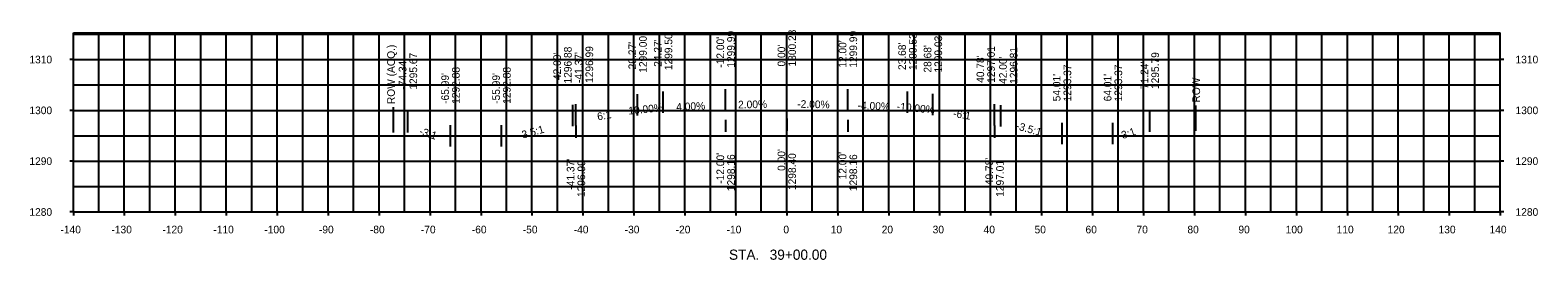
# Model space of a CAD drawing. Extents: x -148 to 147, y 1271 to 1316.
import ezdxf

# ---------------------------------------------------------------- set-up
doc = ezdxf.new("R2010")
doc.units = 0
for name, color, linetype in [('brgPreNewPavement', 7, 'Continuous'), ('BridgeSubstructure', 7, 'Continuous'), ('BridgeSuperStructure', 7, 'Continuous'), ('Default', 7, 'Continuous'), ('OBD_Bridge_Piling', 7, 'Continuous'), ('OBD_D_Super', 7, 'Continuous')]:
    doc.layers.add(name, color=color, linetype=linetype)

msp = doc.modelspace()

# ---------------------------------------------------------------- linework, layer by layer
at = {"layer": 'brgPreNewPavement'}
for p, q in [((-77.18, 1295.64), (-77.18, 1300.64)), ((80.26, 1295.96), (80.26, 1300.96))]:
    msp.add_line(p, q, dxfattribs=at)
at = {"layer": 'BridgeSubstructure'}
for p, q in [((-130, 1280), (-130, 1315.23)), ((-120, 1280), (-120, 1315.23)), ((-110, 1280), (-110, 1315.23)), ((-100, 1280), (-100, 1315.23)), ((-90, 1280), (-90, 1315.23)), ((-80, 1280), (-80, 1315.23)), ((-70, 1280), (-70, 1315.23)), ((-60, 1280), (-60, 1315.23)), ((-50, 1280), (-50, 1315.23)), ((-40, 1280), (-40, 1315.23)), ((-30, 1280), (-30, 1315.23)), ((-20, 1280), (-20, 1315.23)), ((-10, 1280), (-10, 1315.23)), ((0, 1280), (0, 1315.23)), ((10, 1280), (10, 1315.23)), ((20, 1280), (20, 1315.23)), ((30, 1280), (30, 1315.23)), ((40, 1280), (40, 1315.23)), ((50, 1280), (50, 1315.23)), ((60, 1280), (60, 1315.23)), ((70, 1280), (70, 1315.23)), ((80, 1280), (80, 1315.23)), ((90, 1280), (90, 1315.23)), ((100, 1280), (100, 1315.23)), ((110, 1280), (110, 1315.23)), ((120, 1280), (120, 1315.23)), ((130, 1280), (130, 1315.23)), ((-140, 1310), (-140.72, 1310)), ((-140, 1310), (140, 1310)), ((140.72, 1310), (140, 1310)), ((-140, 1300), (-140.72, 1300)), ((-140, 1300), (140, 1300)), ((140.72, 1300), (140, 1300)), ((-140, 1290), (-140.72, 1290)), ((-140, 1290), (140, 1290)), ((140.72, 1290), (140, 1290)), ((-140, 1280), (-140.72, 1280)), ((-140, 1280), (-140, 1279.28)), ((-130, 1280), (-130, 1279.28)), ((-120, 1280), (-120, 1279.28)), ((-110, 1280), (-110, 1279.28)), ((-100, 1280), (-100, 1279.28)), ((-90, 1280), (-90, 1279.28)), ((-80, 1280), (-80, 1279.28)), ((-70, 1280), (-70, 1279.28)), ((-60, 1280), (-60, 1279.28)), ((-50, 1280), (-50, 1279.28)), ((-40, 1280), (-40, 1279.28)), ((-30, 1280), (-30, 1279.28)), ((-20, 1280), (-20, 1279.28)), ((-10, 1280), (-10, 1279.28)), ((0, 1280), (0, 1279.28)), ((10, 1280), (10, 1279.28)), ((20, 1280), (20, 1279.28)), ((30, 1280), (30, 1279.28)), ((40, 1280), (40, 1279.28)), ((50, 1280), (50, 1279.28)), ((60, 1280), (60, 1279.28)), ((70, 1280), (70, 1279.28)), ((80, 1280), (80, 1279.28)), ((90, 1280), (90, 1279.28)), ((100, 1280), (100, 1279.28)), ((110, 1280), (110, 1279.28)), ((120, 1280), (120, 1279.28)), ((130, 1280), (130, 1279.28)), ((140, 1280), (140, 1279.28)), ((140.72, 1280), (140, 1280))]:
    msp.add_line(p, q, dxfattribs=at)
at = {"layer": 'BridgeSuperStructure'}
for p, q in [((-140, 1315.23), (140, 1315.23)), ((-140, 1280), (-140, 1315.23)), ((140, 1280), (140, 1315.23)), ((-140, 1280), (140, 1280))]:
    msp.add_line(p, q, dxfattribs=at)
at = {"layer": 'OBD_Bridge_Piling'}
for p, q in [((-140, 1315), (140, 1315)), ((-135, 1280), (-135, 1315.23)), ((-125, 1280), (-125, 1315.23)), ((-115, 1280), (-115, 1315.23)), ((-105, 1280), (-105, 1315.23)), ((-95, 1280), (-95, 1315.23)), ((-85, 1280), (-85, 1315.23)), ((-75, 1280), (-75, 1315.23)), ((-65, 1280), (-65, 1315.23)), ((-55, 1280), (-55, 1315.23)), ((-45, 1280), (-45, 1315.23)), ((-35, 1280), (-35, 1315.23)), ((-25, 1280), (-25, 1315.23)), ((-15, 1280), (-15, 1315.23)), ((-5, 1280), (-5, 1315.23)), ((5, 1280), (5, 1315.23)), ((15, 1280), (15, 1315.23)), ((25, 1280), (25, 1315.23)), ((35, 1280), (35, 1315.23)), ((45, 1280), (45, 1315.23)), ((55, 1280), (55, 1315.23)), ((65, 1280), (65, 1315.23)), ((75, 1280), (75, 1315.23)), ((85, 1280), (85, 1315.23)), ((95, 1280), (95, 1315.23)), ((105, 1280), (105, 1315.23)), ((115, 1280), (115, 1315.23)), ((125, 1280), (125, 1315.23)), ((135, 1280), (135, 1315.23)), ((-140, 1305), (140, 1305)), ((-140, 1295), (140, 1295)), ((-140, 1285), (140, 1285))]:
    msp.add_line(p, q, dxfattribs=at)
at = {"layer": 'OBD_D_Super'}
for p, q in [((-29.27, 1299), (-29.27, 1303.2)), ((-24.27, 1299.5), (-24.27, 1303.7)), ((-12, 1299.99), (-12, 1304.19)), ((-12, 1299.99), (-12, 1304.19)), ((0, 1300.23), (0, 1304.43)), ((0, 1300.23), (0, 1304.43)), ((0, 1300.23), (0, 1304.43)), ((0, 1300.23), (0, 1304.43)), ((12, 1299.99), (12, 1304.19)), ((12, 1299.99), (12, 1304.19)), ((23.68, 1299.53), (23.68, 1303.73)), ((28.68, 1299.03), (28.68, 1303.23)), ((-74.34, 1295.67), (-74.34, 1299.87)), ((-42, 1296.88), (-42, 1301.08)), ((-41.37, 1296.99), (-41.37, 1301.19)), ((40.78, 1297.01), (40.78, 1301.21)), ((40.78, 1297.01), (40.78, 1301.21)), ((42, 1296.81), (42, 1301.01)), ((71.24, 1295.79), (71.24, 1299.99)), ((-65.99, 1292.88), (-65.99, 1297.08)), ((-55.99, 1292.88), (-55.99, 1297.08)), ((-41.37, 1296.99), (-41.37, 1294.59)), ((-12, 1298.16), (-12, 1295.76)), ((0, 1298.4), (0, 1296)), ((0, 1298.4), (0, 1296)), ((0, 1298.4), (0, 1296)), ((12, 1298.16), (12, 1295.76)), ((40.78, 1297.01), (40.78, 1294.61)), ((54.01, 1293.37), (54.01, 1297.57)), ((64.01, 1293.37), (64.01, 1297.57))]:
    msp.add_line(p, q, dxfattribs=at)

# ---------------------------------------------------------------- texts
at = {"layer": 'brgPreNewPavement'}
for s, p in [('ROW (ACQ.)', (-76.91, 1301.23)), ('ROW', (81.1, 1301.54))]:
    msp.add_text(s, height=1.5, rotation=90, dxfattribs=at).set_placement(p)
at = {"layer": 'Default'}
for s, height, p in [('1310', 1.5, (-148.63, 1309.25)), ('1310', 1.5, (143, 1309.25)), ('1300', 1.5, (-148.63, 1299.25)), ('1300', 1.5, (143, 1299.25)), ('1290', 1.5, (-148.63, 1289.25)), ('1290', 1.5, (143, 1289.25)), ('1280', 1.5, (-148.63, 1279.25)), ('1280', 1.5, (143, 1279.25)), ('-140', 1.5, (-142.53, 1275.8)), ('-130', 1.5, (-132.53, 1275.8)), ('-120', 1.5, (-122.53, 1275.8)), ('-110', 1.5, (-112.53, 1275.8)), ('-100', 1.5, (-102.53, 1275.8)), ('-90', 1.5, (-91.81, 1275.8)), ('-80', 1.5, (-81.81, 1275.8)), ('-70', 1.5, (-71.81, 1275.8)), ('-60', 1.5, (-61.81, 1275.8)), ('-50', 1.5, (-51.81, 1275.8)), ('-40', 1.5, (-41.81, 1275.8)), ('-30', 1.5, (-31.81, 1275.8)), ('-20', 1.5, (-21.81, 1275.8)), ('-10', 1.5, (-11.81, 1275.8)), ('0', 1.5, (-0.67, 1275.8)), ('10', 1.5, (8.62, 1275.8)), ('20', 1.5, (18.62, 1275.8)), ('30', 1.5, (28.62, 1275.8)), ('40', 1.5, (38.62, 1275.8)), ('50', 1.5, (48.62, 1275.8)), ('60', 1.5, (58.62, 1275.8)), ('70', 1.5, (68.62, 1275.8)), ('80', 1.5, (78.62, 1275.8)), ('90', 1.5, (88.62, 1275.8)), ('100', 1.5, (97.9, 1275.8)), ('110', 1.5, (107.9, 1275.8)), ('120', 1.5, (117.9, 1275.8)), ('130', 1.5, (127.9, 1275.8)), ('140', 1.5, (137.9, 1275.8)), ('STA.', 2.004, (-11.34, 1270.6)), ('39+00.00', 2.004, (-3.36, 1270.6))]:
    msp.add_text(s, height=height, dxfattribs=at).set_placement(p)
at = {"layer": 'OBD_D_Super'}
for s, rotation, p in [('1299.00', 90, (-27.47, 1307.4)), ("-24.27'", 90, (-24.57, 1307.9)), ('1299.50', 90, (-22.47, 1307.9)), ("-12.00'", 90, (-12.3, 1308.39)), ("-12.00'", 90, (-12.3, 1308.39)), ('1299.99', 90, (-10.2, 1308.39)), ('1299.99', 90, (-10.2, 1308.39)), ('1300.23', 90, (1.8, 1308.63)), ('1300.23', 90, (1.8, 1308.63)), ('1300.23', 90, (1.8, 1308.63)), ('1300.23', 90, (1.8, 1308.63)), ("12.00'", 90, (11.7, 1308.39)), ("12.00'", 90, (11.7, 1308.39)), ('1299.99', 90, (13.8, 1308.39)), ('1299.99', 90, (13.8, 1308.39)), ('1299.53', 90, (25.48, 1307.93)), ('1299.03', 90, (30.48, 1307.43)), ('1295.67', 90, (-72.54, 1304.07)), ("-42.00'", 90, (-44.32, 1305.28)), ('1296.88', 90, (-42.22, 1305.28)), ("-41.37'", 90, (-40.1, 1305.39)), ('1296.99', 90, (-38, 1305.39)), ("-29.27'", 90, (-29.57, 1307.4)), ("0.00'", 90, (-0.3, 1308.63)), ("0.00'", 90, (-0.3, 1308.63)), ("0.00'", 90, (-0.3, 1308.63)), ("0.00'", 90, (-0.3, 1308.63)), ("23.68'", 90, (23.38, 1307.93)), ("28.68'", 90, (28.38, 1307.43)), ("40.78'", 90, (38.73, 1305.41)), ("40.78'", 90, (38.73, 1305.41)), ('1297.01', 90, (40.83, 1305.41)), ('1297.01', 90, (40.83, 1305.41)), ('1296.81', 90, (45.27, 1305.21)), ('1295.79', 90, (73.04, 1304.19)), ("-74.34'", 90, (-74.64, 1304.07)), ('1292.88', 90, (-64.19, 1301.28)), ('1292.88', 90, (-54.19, 1301.28)), ("42.00'", 90, (43.17, 1305.21)), ('1293.37', 90, (55.81, 1301.77)), ('1293.37', 90, (65.81, 1301.77)), ("71.24'", 90, (70.94, 1304.19)), ("-65.99'", 90, (-66.29, 1301.28)), ("-55.99'", 90, (-56.29, 1301.28)), ("54.01'", 90, (53.71, 1301.77)), ("64.01'", 90, (63.71, 1301.77)), ('2.00%', 1.1458, (-9.54, 1300.37)), ('-2.00%', 358.8542, (2.04, 1300.52)), ('6:1', 9.4642, (-37.08, 1298.03)), ('10.00%', 5.7106, (-31.01, 1299.16)), ('4.00%', 2.2906, (-21.67, 1299.94)), ('-4.00%', 357.7094, (13.87, 1300.25)), ('-10.00%', 354.2894, (21.53, 1300.07)), ('-6:1', 350.5358, (32.57, 1298.71)), ('-3:1', 341.5668, (-72.25, 1295.3)), ('3.5:1', 15.9446, (-51.77, 1294.42)), ('-3.5:1', 344.0554, (44.83, 1296.33)), ('3:1', 18.4332, (65.94, 1294.35)), ("-41.37'", 90, (-41.67, 1284.39)), ('1296.99', 90, (-39.57, 1282.94)), ("-12.00'", 90, (-12.3, 1285.56)), ('1298.16', 90, (-10.2, 1284.1)), ("0.00'", 90, (-0.3, 1288.09)), ("0.00'", 90, (-0.3, 1288.09)), ("0.00'", 90, (-0.3, 1288.09)), ('1298.40', 90, (1.8, 1284.32)), ('1298.40', 90, (1.8, 1284.32)), ('1298.40', 90, (1.8, 1284.32)), ("12.00'", 90, (11.7, 1286.42)), ('1298.16', 90, (13.8, 1284.1)), ("40.78'", 90, (40.48, 1285.27)), ('1297.01', 90, (42.58, 1282.98))]:
    msp.add_text(s, height=1.5, rotation=rotation, dxfattribs=at).set_placement(p)

doc.saveas('drawing.dxf')
